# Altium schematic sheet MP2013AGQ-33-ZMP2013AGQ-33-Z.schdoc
size 127 x 101 mm
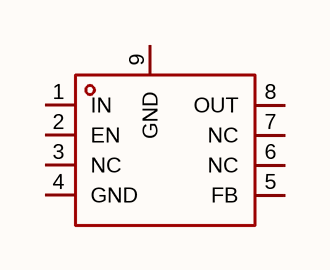
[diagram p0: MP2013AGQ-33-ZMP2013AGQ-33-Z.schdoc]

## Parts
U?  mp2013agq-33-z  [DFN-8_L3.0-W3.0-P0.65-BL-EP-2]  (value not drawn)

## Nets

Not connected (* = marked no-connect by the designer): U? 1(IN) 2(EN) 3(NC) 4(GND) 5(FB) 6(NC) 7(NC) 8(OUT) 9(GND)

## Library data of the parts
U? = mp2013agq-33-z: 输出极性:正极;工作电压:40V;输出电压:3.3V;输出电流:150mA;电源纹波抑制比(PSRR):58dB@(100Hz);输出类型:固定;; Manufacturer: MPS(芯源); AddInBom: yes; ModelId: 66f3299fc7f14fd2a1190a8b2d3ce3ec; ModelTransform: 118.11,118.8974,0,0,0,0,0,0,0; Output Configuration: 正极; Voltage - Supply: 40V; Output Voltage: 3.3V; Output Current: 150mA; Voltage Dropout: 700mV@(150mA); standby current: 3.3uA; Output Type: 固定; Number of Outputs: 1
